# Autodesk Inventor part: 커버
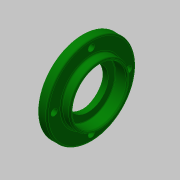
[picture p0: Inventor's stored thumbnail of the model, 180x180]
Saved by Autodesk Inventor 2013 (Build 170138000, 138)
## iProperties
Created: 2018-11
Part Number: 커버
Material: 알루미늄 6061
Document SubType Name: Modeling
Designer: mduedu
Density: 1 g/cm^3
Author: mduedu
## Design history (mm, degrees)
sketch "스케치1"
  geometry: L1 (0, 0)-(2, 0); L2 (2, 0)-(2, 20); L3 (2, 20)-(0, 20); L4 (0, 20)-(0, 0); L5 (2, 0)-(8, 0); L6 (8, 0)-(8, 31); L7 (8, 31)-(2, 31); L8 (2, 31)-(2, 0); L9 (8, 0)-(14, 0); L10 (14, 0)-(14, 21); L11 (14, 21)-(8, 21); L12 (8, 21)-(8, 0)
  constraints: 24 end point, 6 parallel, 3 horizontal, 3 perpendicular
  dimensions: "d0" = 62 diameter of L7 L5; "d2" = 42 diameter of L11 L9; "d3" = 40 diameter of L3 L1; "d4" = 2 distance of L2.end L3.end; "d5" = 6 distance of L6.end L7.end; "d6" = 14 distance between parallel lines of L10 L4
revolve "회전1" sketch "스케치1" stored, may be unused: angle "d7" = 90 deg
sketch "스케치2"
  geometry: L1 (0, -20)-(0, 20) reference; L2 (0, 20)-(2, 20) reference; L3 (2, 20)-(2, 31) reference; L4 (2, 31)-(8, 31) reference; L5 (8, 31)-(8, 21) reference; L6 (8, 21)-(14, 21) reference; L7 (14, 21)-(14, -21) reference; L8 (14, -21)-(8, -21) reference; L9 (8, -21)-(8, -31) reference; L10 (8, -31)-(2, -31) reference; L11 (2, -31)-(2, -20) reference; L12 (2, -20)-(0, -20) reference; L13 (0, 0)-(2, 0); L14 (2, 0)-(2, 16.5); L15 (2, 16.5)-(0, 16.5); L16 (0, 16.5)-(0, 0); L17 (2, 0)-(5.7, 0); L18 (5.7, 0)-(5.7, 14); L19 (5.7, 14)-(2, 14); L20 (2, 14)-(2, 0); L21 (5.7, 0)-(14, 0); L22 (14, 0)-(14, 19); L23 (14, 19)-(5.7, 19); L24 (5.7, 19)-(5.7, 0)
  constraints: 24 end point, 6 parallel, 3 horizontal, 3 perpendicular, 1 point on line
  dimensions: "d8" = 38 diameter of L23 L21; "d10" = 28 diameter of L19 L17; "d11" = 33 diameter of L15 L13; "d12" = 2 distance of L14.end L15.end; "d13" = 8.3 distance of L22.end L23.end
revolve "회전2" sketch "스케치2" stored, may be unused: angle "d14" = 90 deg
fillet "모깎기1" dims "d15" = 0.3
chamfer "모따기1" distance "d16" = 0.8; stored, may be unused: second distance "d17" = 2, angle "d18" = 30 deg
fillet "모깎기2" dims "d19" = 1
chamfer "모따기2" distance "d20" = 0.5; stored, may be unused: second distance "d21" = 2, angle "d22" = 30 deg
sketch "스케치3" dims "d23" = 52
  geometry: 6 further points
  constraints: 2 vertical alignment, 1 coincident, 7 other
  dimensions: "d26" = 360 deg dimension on point (0, 0) point (0, 26) (derived)
sketch "스케치4"
  geometry: 4 further points
  constraints: 4 other
hole "구멍1" sketch "스케치4" at (-26, 0), (0, -26), (26, 0), (0, 26) diameter "d28" = 4.5; stored, may be unused: countersink angle "d32" = 90 deg, drill point angle "d34" = 0 deg; dims "d29" = 6, "d30" = 8, "d31" = 4.6, "d33" = 8
node "솔리드1"
node "절단 모서리 투영1"
